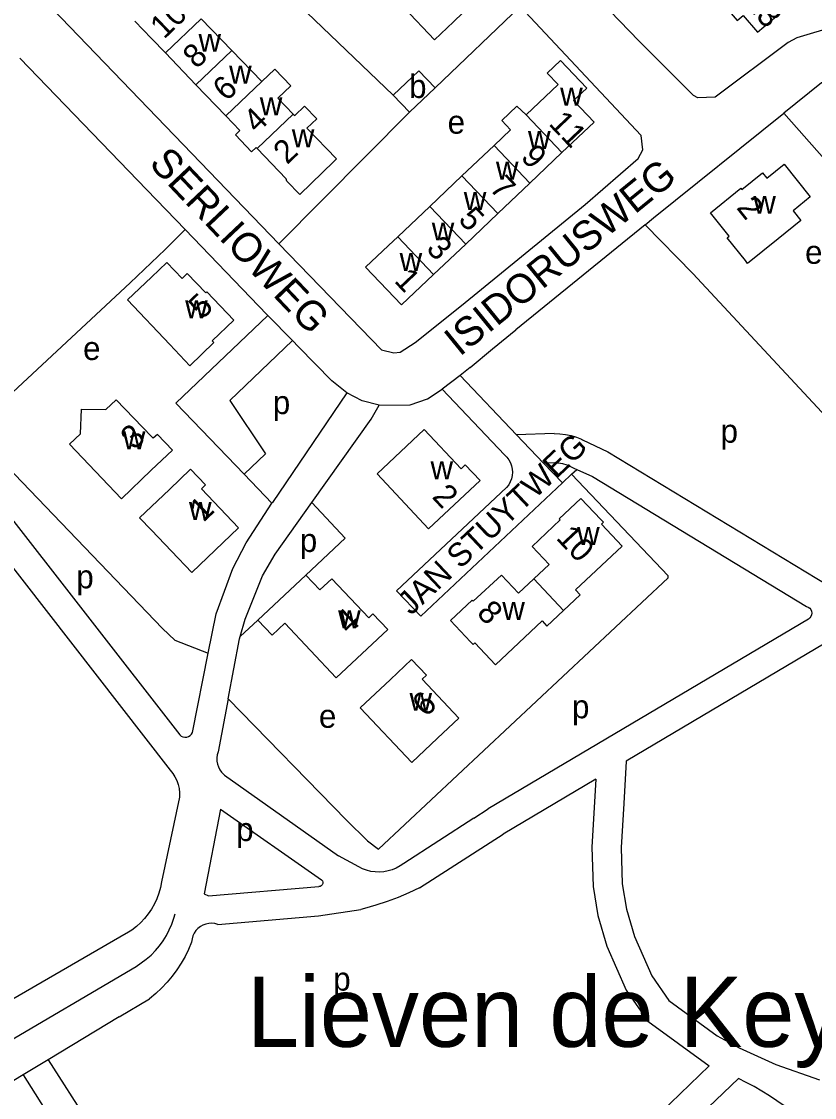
# Model space of a CAD drawing. Extents: x 158848 to 160613, y 385889 to 387762.
# Drawn here: x 159977.8 to 160113.5, y 386225.4 to 386409.7 of the extents above; entities that cross this region are included whole.
import ezdxf

# ---------------------------------------------------------------- set-up
doc = ezdxf.new("R2010")
doc.units = 0
for name, color, linetype in [('BLT_Basislijn', 7, 'Continuous'), ('BLT_Bebouwing', 7, 'Continuous'), ('BLT_Centroide', 7, 'Continuous'), ('BLT_Huisnummer', 7, 'Continuous'), ('BLT_Huisnummer_ tussenligend', 7, 'Continuous'), ('BLT_Onderverdeling_panden', 7, 'Continuous'), ('BLT_Sport_parknaam', 7, 'Continuous'), ('BLT_Straatnaam', 7, 'Continuous'), ('BLT_Straatnaam_verkleind', 7, 'Continuous')]:
    doc.layers.add(name, color=color, linetype=linetype)

msp = doc.modelspace()

# ---------------------------------------------------------------- linework, layer by layer
at = {"layer": 'BLT_Basislijn'}
for p, q in [((160001.18, 386435.67), (160041.38, 386397.03)), ((160063.11, 386412.2), (160048.57, 386398.28)), ((159977.49, 386403.38), (159999.23, 386380.81)), ((160021.79, 386371.56), (160044.16, 386394.1)), ((159999.23, 386380.81), (160005.77, 386374.03)), ((160019.77, 386359.46), (160005.77, 386374.03)), ((160084.49, 386374.85), (160062.36, 386356.85)), ((159945.87, 386363.37), (160004.86, 386287.49)), ((159942.68, 386359.33), (160003.21, 386281.47)), ((160019.92, 386359.3), (160019.77, 386359.46)), ((160024.15, 386355.01), (160019.92, 386359.3)), ((160058.34, 386353.59), (160062.36, 386356.85)), ((160025.18, 386353.96), (160024.15, 386355.01)), ((160054.52, 386350.38), (160058.34, 386353.59)), ((160054.52, 386350.38), (160052.82, 386349.06)), ((160052.82, 386349.06), (160049.78, 386346.7)), ((160062.5, 386338.89), (160052.82, 386349.06)), ((160033.42, 386346.08), (160020.7, 386327.31)), ((160060.44, 386335.44), (160049.78, 386346.7)), ((160068.9, 386339.11), (160062.5, 386338.89)), ((160067.12, 386334.04), (160062.5, 386338.89)), ((160073.77, 386338.04), (160078.08, 386335.99)), ((160078.08, 386335.99), (160118.02, 386311.75)), ((160068.92, 386334.11), (160067.12, 386334.04)), ((160070.35, 386330.65), (160067.12, 386334.04)), ((160071.9, 386332.12), (160072.79, 386332.95)), ((160072.27, 386333.19), (160072.79, 386332.95)), ((160072.79, 386332.95), (160075.49, 386331.72)), ((160015.88, 386332.14), (160020.63, 386327.2)), ((160070.35, 386330.65), (160071.9, 386332.12)), ((160075.49, 386331.72), (160112.11, 386309.49)), ((160020.63, 386327.2), (160020.7, 386327.31)), ((160018.24, 386307.13), (160015.2, 386304.37)), ((160112.44, 386307.33), (160057.62, 386274.81)), ((160116.83, 386304.12), (160081.26, 386283.02)), ((160007.01, 386287.91), (160009.72, 386301.49)), ((160013.14, 386293.66), (160011.41, 386284.59)), ((160012.52, 386280.6), (160032, 386266.76)), ((160076.07, 386279.93), (160060.18, 386270.51)), ((160004.8, 386276.86), (160001.72, 386262.31)), ((160011.84, 386274.79), (160029.13, 386262.67)), ((160055.2, 386273.25), (160057.62, 386274.81)), ((160055.2, 386273.25), (160043.17, 386265.48)), ((160045.88, 386261.28), (160060.18, 386270.51)), ((160035.5, 386264.88), (160032, 386266.76)), ((160009.8, 386259.93), (160028.65, 386261.54)), ((160028.61, 386256.54), (160035.83, 386257.61)), ((160011.35, 386255.05), (160028.61, 386256.54)), ((159995.67, 386253.46), (159976.29, 386242.27)), ((159972.83, 386233.41), (159997.37, 386247.86)), ((159994.47, 386239.19), (159999.69, 386242.32)), ((159994.47, 386239.19), (159982.35, 386231.88)), ((159982.35, 386231.88), (159978.08, 386229.3)), ((159982.35, 386231.88), (160012.37, 386184.83)), ((160070.09, 386206.44), (160095.42, 386230.8)), ((159978.08, 386229.3), (159975.13, 386227.52)), ((159978.08, 386229.3), (160007.98, 386181.84)), ((160046.46, 386176.77), (160100.43, 386228.68))]:
    msp.add_line(p, q, dxfattribs=at)
for points in [[(159975.08, 386460.67), (159958.35, 386444.96), (159956.97, 386442.82), (159956.86, 386440.03), (159962.17, 386433.57), (160021.79, 386371.56)], [(160181.86, 386420.71), (160155.01, 386402.26), (160151.89, 386401.53), (160147.92, 386401.69), (160130.32, 386408.37), (160125.71, 386409.25), (160119.49, 386409.25), (160117.12, 386408.85), (160110.44, 386406.85), (160108.94, 386406.05), (160096.44, 386396.7), (160093.52, 386396.6), (160092.73, 386396.97), (160083.46, 386406.29), (160065.04, 386425.4)], [(160021.79, 386371.56), (160039.4, 386353.42), (160041.49, 386352.9), (160042.58, 386353.01), (160045.16, 386354.66), (160053.07, 386361.02), (160074.23, 386378.29), (160083.27, 386386.2), (160084.09, 386387.66), (160083.81, 386390.16), (160063.11, 386412.2)], [(160130.46, 386398.54), (160123.83, 386400.82), (160118.33, 386400.5), (160114.67, 386399.15), (160108.2, 386393.95)], [(160108.2, 386393.95), (160115.15, 386386.1), (160115.53, 386386.1), (160130.46, 386398.54)], [(160084.49, 386374.85), (160085.94, 386376.04), (160108.2, 386393.95)], [(160084.49, 386374.85), (160092.67, 386366.48), (160142.83, 386312.53), (160143.72, 386311.97), (160144.35, 386312.13), (160171.61, 386330.59), (160220.56, 386364.05), (160220.56, 386364.47), (160207.47, 386383.23)], [(160005.77, 386374.03), (160002.38, 386370.61), (159996.35, 386364.89), (159976.27, 386346.18), (159969.84, 386339.65), (159969.84, 386339.11), (160001.89, 386305.69), (160004.01, 386303.7), (160009.72, 386301.49)], [(160019.92, 386359.3), (160004.2, 386344.3), (160015.88, 386332.14)], [(160024.15, 386355.01), (160013.4, 386344.77), (160019.5, 386335.6), (160015.88, 386332.14)], [(160033.42, 386346.08), (160030.88, 386348.11), (160025.18, 386353.96)], [(160038.96, 386343.94), (160036.08, 386344.72), (160033.42, 386346.08)], [(160038.96, 386343.94), (160044.26, 386344.03), (160047.24, 386345.05), (160049.78, 386346.7)], [(160027.48, 386327.3), (160037.62, 386341.56), (160038.96, 386343.94)], [(160068.9, 386339.11), (160069.9, 386339.06), (160070.85, 386338.94), (160071.8, 386338.74), (160072.72, 386338.46), (160073.62, 386338.11), (160073.77, 386338.04)], [(160060.44, 386335.44), (160060.83, 386335.04), (160061.17, 386334.59), (160061.43, 386334.09), (160061.62, 386333.57), (160061.74, 386333.02), (160061.77, 386332.46), (160061.73, 386331.9), (160061.61, 386331.35), (160061.41, 386330.83), (160061.14, 386330.34), (160060.75, 386329.84)], [(160068.92, 386334.11), (160069.65, 386334.06), (160070.37, 386333.94), (160071.07, 386333.74), (160071.74, 386333.47), (160072.27, 386333.19)], [(160013.14, 386293.66), (160033.4, 386272.87), (160036.98, 386269.37), (160038.86, 386267.93), (160088.4, 386314.39), (160088.4, 386314.74), (160071.9, 386332.12)], [(160060.75, 386329.84), (160041.96, 386312.15), (160046.09, 386307.8), (160070.35, 386330.65)], [(160009.72, 386301.49), (160011.11, 386308.25), (160013.96, 386315.96), (160016.24, 386320.36), (160020.63, 386327.2)], [(160015.2, 386304.37), (160016.04, 386307.29), (160019, 386314.72), (160021.18, 386318.44), (160027.48, 386327.3)], [(160026.45, 386314.86), (160033.14, 386321.2), (160027.48, 386327.3)], [(160112.11, 386309.49), (160112.39, 386309.37), (160112.64, 386309.19), (160112.83, 386308.95), (160112.95, 386308.66), (160113, 386308.36), (160112.96, 386308.05), (160112.85, 386307.76), (160112.67, 386307.52), (160112.44, 386307.33)], [(160013.14, 386293.66), (160015.08, 386303.95), (160015.2, 386304.37)], [(160004.86, 386287.49), (160005.11, 386287.29), (160005.41, 386287.16), (160005.73, 386287.11), (160006.05, 386287.13), (160006.36, 386287.23), (160006.63, 386287.41), (160006.85, 386287.64), (160007.01, 386287.91)], [(160011.41, 386284.59), (160011.26, 386284.08), (160011.19, 386283.55), (160011.2, 386283.02), (160011.29, 386282.5), (160011.46, 386282), (160011.7, 386281.53), (160012.01, 386281.1), (160012.38, 386280.72), (160012.52, 386280.6)], [(160003.21, 386281.47), (160003.65, 386280.91), (160004.03, 386280.31), (160004.34, 386279.67), (160004.57, 386279), (160004.73, 386278.3), (160004.81, 386277.59), (160004.8, 386276.86)], [(160081.26, 386283.02), (160080.82, 386275.72), (160080.37, 386268.19), (160080.57, 386262), (160081.28, 386257.67), (160082.64, 386253), (160085.62, 386246.23), (160088.56, 386242.01), (160096.81, 386235.97), (160100.58, 386233.89), (160106.85, 386231.04), (160114.31, 386228.43)], [(160076.07, 386279.93), (160075.37, 386268.27), (160075.58, 386261.51), (160076.4, 386256.56), (160077.93, 386251.29), (160081.24, 386243.77), (160084.93, 386238.47), (160095.42, 386230.8)], [(160011.84, 386274.79), (160009.02, 386260.29), (160009.8, 386259.93)], [(160043.17, 386265.48), (160042.56, 386265.05), (160041.9, 386264.69), (160041.22, 386264.4), (160040.5, 386264.19), (160039.77, 386264.05), (160039.03, 386264), (160038.28, 386264.03), (160037.54, 386264.13), (160036.82, 386264.31), (160036.12, 386264.57), (160035.5, 386264.88)], [(160001.72, 386262.31), (160001.54, 386261.34), (160001.27, 386260.38), (160000.93, 386259.45), (160000.51, 386258.55), (160000.02, 386257.68), (159999.47, 386256.86), (159998.85, 386256.08), (159998.17, 386255.36), (159997.43, 386254.69), (159996.65, 386254.08), (159995.81, 386253.54), (159995.67, 386253.46)], [(160029.13, 386262.67), (160029.27, 386262.48), (160029.33, 386262.26), (160029.32, 386262.03), (160029.22, 386261.83), (160029.06, 386261.66), (160028.86, 386261.56), (160028.65, 386261.54)], [(160045.88, 386261.28), (160044.06, 386260.43), (160042.21, 386259.65), (160040.33, 386258.95), (160038.42, 386258.32), (160036.49, 386257.77), (160035.83, 386257.61)], [(159997.37, 386247.86), (159998.27, 386248.44), (159999.13, 386249.08), (159999.94, 386249.78), (160000.69, 386250.55), (160001.38, 386251.36), (160002.01, 386252.23), (160002.58, 386253.14), (160003.07, 386254.09), (160003.49, 386255.08), (160003.84, 386256.09), (160004.05, 386256.88)], [(160011.35, 386255.05), (160010.85, 386255.18), (160010.34, 386255.24), (160009.82, 386255.22), (160009.32, 386255.11), (160008.83, 386254.93), (160008.38, 386254.68), (160007.97, 386254.37), (160007.62, 386253.99), (160007.33, 386253.56), (160007.1, 386253.1), (160006.96, 386252.6), (160006.88, 386252.01)], [(160006.88, 386252.01), (160006.36, 386250.77), (160005.76, 386249.56), (160005.09, 386248.38), (160004.36, 386247.25), (160003.55, 386246.17), (160002.69, 386245.13), (160001.76, 386244.15), (160000.78, 386243.23), (159999.69, 386242.32)], [(160117.34, 386215.72), (160116.32, 386216.85), (160115.26, 386217.96), (160114.18, 386219.03), (160113.06, 386220.08), (160111.91, 386221.1), (160110.73, 386222.08), (160109.53, 386223.04), (160108.29, 386223.95), (160107.04, 386224.83), (160105.76, 386225.68), (160104.45, 386226.49), (160103.13, 386227.26), (160101.79, 386227.99), (160100.43, 386228.68)]]:
    msp.add_lwpolyline(points, dxfattribs=at)
at = {"layer": 'BLT_Bebouwing'}
for p, q in [((159997.17, 386409.73), (160000, 386406.76)), ((160008.5, 386410.11), (160013.75, 386404.68)), ((160002.39, 386404.27), (160000, 386406.76)), ((160007.63, 386398.82), (160002.39, 386404.27)), ((160013.75, 386404.68), (160018.88, 386399.37)), ((160012.76, 386393.51), (160007.63, 386398.82)), ((160048.57, 386398.28), (160044.16, 386394.1)), ((160044.16, 386394.1), (160041.38, 386397.03)), ((160053.14, 386383.22), (160058.63, 386388.44)), ((160064.76, 386381.99), (160070.25, 386387.2)), ((160047.65, 386378), (160053.14, 386383.22)), ((160059.27, 386376.77), (160064.76, 386381.99)), ((160042.15, 386372.79), (160047.65, 386378)), ((160053.78, 386371.55), (160059.27, 386376.77)), ((160048.28, 386366.33), (160053.78, 386371.55)), ((159995.93, 386361.98), (160000, 386365.85)), ((160018.24, 386307.13), (160026.45, 386314.86))]:
    msp.add_line(p, q, dxfattribs=at)
for points in [[(160100.21, 386409.81), (160101.26, 386410.7), (160103.69, 386407.84), (160109.1, 386412.41), (160106.63, 386415.33), (160106.21, 386414.98), (160098.57, 386424.01), (160095.48, 386421.4), (160093.68, 386419.87), (160092.52, 386418.89), (160100.21, 386409.81)], [(160049.68, 386418.12), (160054.9, 386412.66), (160051.71, 386409.61), (160048.46, 386406.51), (160043.24, 386411.98)], [(160064.12, 386393.66), (160069.58, 386398.84), (160067.7, 386400.82), (160069.99, 386402.99), (160074.5, 386398.25), (160072.24, 386396.1), (160075.74, 386392.42), (160070.25, 386387.2)], [(160018.88, 386399.37), (160021.1, 386401.5), (160023.85, 386398.63), (160021.64, 386396.52), (160024.26, 386393.81)], [(160041.38, 386397.03), (160045.79, 386401.21), (160048.57, 386398.28)], [(160024.26, 386393.81), (160024.52, 386393.54), (160026.21, 386395.16), (160028.29, 386393.01), (160026.6, 386391.39), (160031.68, 386386.14), (160031.38, 386385.85), (160031.2, 386385.68), (160025.38, 386380.03), (160023.16, 386382.3), (160023.06, 386382.74), (160018.1, 386387.92)], [(160058.63, 386388.44), (160061.46, 386391.13), (160059.99, 386392.73), (160062.53, 386395.14), (160064.12, 386393.66)], [(160018.1, 386387.92), (160017.95, 386388.08), (160017.15, 386387.32), (160014.37, 386390.24), (160015.16, 386391), (160012.76, 386393.51)], [(160107.24, 386372.43), (160102.02, 386368.24), (160101.64, 386368.72), (160098.51, 386372.61), (160098.86, 386372.9), (160095.64, 386376.9), (160100.83, 386381.1), (160101.02, 386380.89), (160104.54, 386383.75), (160105.3, 386382.83), (160108.25, 386385.22), (160112.74, 386379.62), (160109.79, 386377.25), (160111.14, 386375.56), (160107.24, 386372.43)], [(160042.15, 386372.79), (160040.57, 386371.28), (160036.66, 386367.57), (160042.79, 386361.12), (160048.28, 386366.33)], [(160000, 386365.85), (160002.66, 386368.38), (160005.27, 386365.65), (160006.15, 386366.48), (160009.32, 386363.18), (160009.51, 386363.38), (160014.13, 386358.54), (160010.4, 386354.98), (160010.7, 386354.67), (160006.59, 386350.72), (160003.15, 386354.35), (159995.93, 386361.98)], [(159999.99, 386332.82), (159994.87, 386327.93), (159985.97, 386337.26), (159987.85, 386339.05), (159988.02, 386343.25), (159992.22, 386343.22), (159993.96, 386344.89), (160000, 386338.61)], [(159999.99, 386332.82), (160003.6, 386336.27), (160001.05, 386338.94), (160000.32, 386338.28), (160000, 386338.61)], [(160046.7, 386339.77), (160052.99, 386333.06), (160053.71, 386333.74), (160056.26, 386331.04), (160047.44, 386322.77), (160038.61, 386332.18), (160046.7, 386339.77)], [(160000, 386322.53), (160003.45, 386318.93), (160006.91, 386315.33), (160014.89, 386322.98), (160008.55, 386329.63), (160009.24, 386330.33), (160006.7, 386333.01), (160003.09, 386329.54), (160000, 386326.58)], [(160070.51, 386308.8), (160073.36, 386311.47), (160072.55, 386312.33), (160080.55, 386319.83), (160077.02, 386323.6), (160077.34, 386323.9), (160076.91, 386324.36), (160073.48, 386328), (160069.77, 386324.51), (160069.97, 386324.31), (160065.15, 386319.78), (160068.05, 386316.68), (160065.43, 386314.23)], [(160000, 386322.53), (159997.98, 386324.64), (160000, 386326.58)], [(160026.45, 386314.86), (160028.85, 386312.31), (160030.89, 386314.23)], [(160065.43, 386314.23), (160062.81, 386311.78), (160059.91, 386314.87), (160055.03, 386310.41), (160054.89, 386310.56), (160051.18, 386307.07), (160054.6, 386303.43), (160055.04, 386302.96), (160055.36, 386303.26), (160058.87, 386299.51), (160066.86, 386307), (160067.66, 386306.13), (160070.51, 386308.8)], [(160030.89, 386314.23), (160037.19, 386307.54), (160037.91, 386308.2), (160040.45, 386305.53), (160031.64, 386297.25), (160022.81, 386306.63), (160020.64, 386304.58), (160018.24, 386307.13)], [(160048.98, 386286.92), (160044.56, 386282.76), (160035.73, 386292.14), (160040.89, 386296.99), (160044.52, 386300.42), (160047.05, 386297.73), (160046.35, 386297.05), (160052.62, 386290.35), (160048.98, 386286.92)]]:
    msp.add_lwpolyline(points, dxfattribs=at)
at = {"layer": 'BLT_Onderverdeling_panden'}
for p, q in [((160002.39, 386404.27), (160008.5, 386410.11)), ((160007.63, 386398.82), (160013.75, 386404.68)), ((160012.76, 386393.51), (160018.88, 386399.37)), ((160018.1, 386387.92), (160024.26, 386393.81)), ((160070.25, 386387.2), (160064.12, 386393.66)), ((160064.76, 386381.99), (160058.63, 386388.44)), ((160059.27, 386376.77), (160053.14, 386383.22)), ((160053.78, 386371.55), (160047.65, 386378)), ((160048.28, 386366.33), (160042.15, 386372.79)), ((160065.43, 386314.23), (160070.51, 386308.8))]:
    msp.add_line(p, q, dxfattribs=at)

# ---------------------------------------------------------------- texts
at = {"layer": 'BLT_Centroide'}
for s, p in [('w', (160008.06, 386404.47)), ('w', (160013.3, 386399.03)), ('b', (160044.1, 386396.56)), ('w', (160069.94, 386395.23)), ('w', (160018.55, 386393.59)), ('e', (160050.69, 386390.44)), ('w', (160024.03, 386388.12)), ('w', (160064.44, 386387.81)), ('w', (160058.95, 386382.59)), ('w', (160053.45, 386377.38)), ('w', (160102.99, 386376.72)), ('w', (160047.97, 386372.16)), ('w', (160042.47, 386366.94)), ('e', (160111.85, 386368.16)), ('w', (160005.78, 386358.84)), ('e', (159988.32, 386351.69)), ('p', (160020.78, 386342.43)), ('p', (160097.39, 386337.53)), ('w', (159995.12, 386336.41)), ('w', (160047.76, 386331.28)), ('w', (160006.44, 386324.28)), ('p', (160025.4, 386318.82)), ('w', (160072.84, 386320.02)), ('p', (159987.16, 386312.59)), ('w', (160060.04, 386307.19)), ('w', (160031.95, 386305.75)), ('w', (160044.17, 386291.62)), ('p', (160071.97, 386290.34)), ('e', (160028.67, 386288.71)), ('p', (160014.51, 386269.32)), ('p', (160031.12, 386243.71))]:
    msp.add_text(s, height=4, dxfattribs=at).set_placement(p)
at = {"layer": 'BLT_Huisnummer'}
for s, rotation, p in [('13', 310.2508, (160101.37, 386412.81)), ('10', 43.9646, (160002.15, 386406.5)), ('6', 43.9646, (160012.86, 386395.84)), ('11', 313.5251, (160067.84, 386392.05)), ('2', 43.9646, (160023.22, 386385.04)), ('2', 308.7469, (160099.98, 386377.73)), ('5', 313.5251, (160052.35, 386375.6)), ('1', 313.5251, (160041.4, 386365.15)), ('5', 43.7029, (160008.7, 386358.52)), ('3', 43.6708, (159997.07, 386336.15)), ('2', 313.1844, (160047.87, 386328.17)), ('1', 43.8051, (160008.87, 386323.76)), ('10', 313.1194, (160069.1, 386321.12)), ('4', 43.2399, (160033.81, 386304.58)), ('8', 313.129, (160055.5, 386308.24)), ('6', 43.2788, (160046.94, 386290.41))]:
    msp.add_text(s, height=4, rotation=rotation, dxfattribs=at).set_placement(p)
at = {"layer": 'BLT_Huisnummer_ tussenligend'}
for s, rotation, p in [('8', 43.9646, (160007.74, 386401.41)), ('4', 43.9646, (160018.08, 386390.38)), ('9', 313.5251, (160063.03, 386386.29)), ('7', 313.5251, (160057.68, 386380.96)), ('3', 313.5251, (160046.86, 386370.61))]:
    msp.add_text(s, height=4, rotation=rotation, dxfattribs=at).set_placement(p)
at = {"layer": 'BLT_Sport_parknaam'}
msp.add_text('Lieven de Keypark', height=12, dxfattribs=at).set_placement((160016.34, 386234.08))
at = {"layer": 'BLT_Straatnaam'}
for s, rotation, p in [('SERLIOWEG', 313.4581, (159999.43, 386385.18)), ('ISIDORUSWEG', 39.1188, (160052.75, 386352.18))]:
    msp.add_text(s, height=5, rotation=rotation, dxfattribs=at).set_placement(p)
at = {"layer": 'BLT_Straatnaam_verkleind'}
msp.add_text('JAN STUYTWEG', height=4, rotation=43.2903, dxfattribs=at).set_placement((160044.42, 386307.84))

doc.saveas('drawing.dxf')
